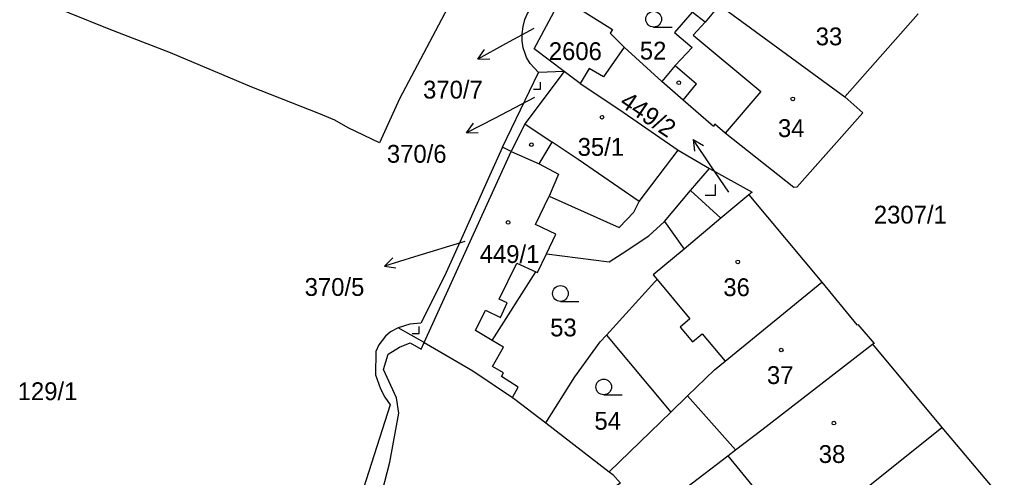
# Model space of a CAD drawing. Extents: x -679220 to -673243, y -1075091 to -1066557.
# Drawn here: x -676654 to -676560.9, y -1071402.6 to -1071358.9 of the extents above; entities that cross this region are included whole.
import ezdxf

# ---------------------------------------------------------------- set-up
doc = ezdxf.new("R2010")
doc.units = 0
for name, color, linetype in [('Hranice parcel', 7, 'Continuous'), ('Parcelní čísla', 7, 'Continuous'), ('Pop  PČ popisy', 7, 'Continuous'), ('Vnitřní kresba', 7, 'Continuous'), ('Značky budov', 7, 'Continuous'), ('Značky kultur', 7, 'Continuous')]:
    doc.layers.add(name, color=color, linetype=linetype)

msp = doc.modelspace()

# ---------------------------------------------------------------- linework, layer by layer
at = {"layer": 'Hranice parcel'}
for p, q in [((-676568.31, -1071358.37), (-676575.3, -1071366.28)), ((-676592.76, -1071364.8), (-676596.34, -1071361.54)), ((-676604.52, -1071363.95), (-676605.31, -1071363.11)), ((-676607.93, -1071371.09), (-676604.52, -1071363.95)), ((-676602.05, -1071363.86), (-676604.52, -1071363.95)), ((-676600.53, -1071365), (-676602.05, -1071363.86)), ((-676615.42, -1071389.7), (-676607.13, -1071371.5)), ((-676607.13, -1071371.5), (-676607.93, -1071371.09)), ((-676591.2, -1071371.36), (-676588.21, -1071373.1)), ((-676584.46, -1071375.63), (-676577.5, -1071383.95)), ((-676592.51, -1071378.17), (-676590.63, -1071380.8)), ((-676615.42, -1071389.7), (-676617.88, -1071388.31)), ((-676598.04, -1071389), (-676591.9, -1071396.34)), ((-676572.66, -1071389.87), (-676566.05, -1071397.82)), ((-676591.9, -1071396.34), (-676597.79, -1071402.04)), ((-676603.81, -1071397.35), (-676597.79, -1071402.04)), ((-676574.86, -1071404.84), (-676566.05, -1071397.82)), ((-676566.05, -1071397.82), (-676558.15, -1071407.15))]:
    msp.add_line(p, q, dxfattribs=at)
for points in [[(-676610.67, -1071352.37), (-676612.63, -1071356.71), (-676617.76, -1071366.46), (-676619.68, -1071370.65), (-676622.67, -1071369.24), (-676623.92, -1071368.49), (-676625.45, -1071367.86), (-676631.86, -1071365.36), (-676639.6, -1071362.09), (-676645.45, -1071359.81), (-676653.02, -1071356.73)], [(-676605.31, -1071363.11), (-676605.644, -1071362.522), (-676605.764, -1071362.245), (-676605.966, -1071361.599), (-676606.07, -1071360.93), (-676606.077, -1071360.268), (-676605.987, -1071359.569), (-676605.8, -1071358.89), (-676605.552, -1071358.315), (-676605.215, -1071357.786), (-676604.799, -1071357.318), (-676604.761, -1071357.281), (-676604.27, -1071356.892), (-676603.723, -1071356.585), (-676603.135, -1071356.37), (-676602.52, -1071356.25)], [(-676602.05, -1071363.86), (-676604.91, -1071361.71), (-676602.33, -1071356.8), (-676600.25, -1071358.11)], [(-676587.35, -1071357.64), (-676588.63, -1071359.16), (-676589.87, -1071358.19), (-676591.54, -1071360.13), (-676589.87, -1071361.56), (-676591.49, -1071363.3), (-676592.76, -1071364.8)], [(-676587.35, -1071357.64), (-676587.24, -1071357.52), (-676575.3, -1071366.28)], [(-676600.25, -1071358.11), (-676597.47, -1071359.85), (-676597.69, -1071360.21), (-676596.34, -1071361.54)], [(-676596.34, -1071361.54), (-676598.33, -1071364.37), (-676599.68, -1071363.56), (-676600.53, -1071365)], [(-676602.05, -1071363.86), (-676605.8, -1071368.85), (-676607.13, -1071371.5)], [(-676600.53, -1071365), (-676596.84, -1071367.45), (-676591.2, -1071371.36)], [(-676575.3, -1071366.28), (-676573.58, -1071367.8), (-676579.87, -1071374.9), (-676580.18, -1071374.91), (-676586.72, -1071369.74), (-676587.7, -1071368.89), (-676587.83, -1071369.1), (-676590.72, -1071366.58), (-676592.76, -1071364.8)], [(-676607.93, -1071371.09), (-676609.2, -1071373.82), (-676611.68, -1071379.45), (-676613.49, -1071383.37), (-676615.74, -1071387.86), (-676616.79, -1071387.96), (-676617.88, -1071388.31)], [(-676607.13, -1071371.5), (-676604.45, -1071372.65), (-676602.6, -1071373.65), (-676603.48, -1071375.76), (-676596.81, -1071378.73), (-676595.42, -1071377.26), (-676594.93, -1071376.27), (-676591.2, -1071371.36)], [(-676592.51, -1071378.17), (-676590.02, -1071375.2), (-676588.21, -1071373.1)], [(-676588.21, -1071373.1), (-676584.13, -1071375.35), (-676584.46, -1071375.63)], [(-676584.46, -1071375.63), (-676587.13, -1071377.86), (-676590.63, -1071380.8)], [(-676607, -1071394.96), (-676606.44, -1071393.97), (-676608.03, -1071392.93), (-676607.84, -1071392.6), (-676608.89, -1071392), (-676607.84, -1071390.16), (-676608.92, -1071389.51), (-676604.76, -1071382.97), (-676604.6, -1071383.04), (-676603.74, -1071381.24), (-676597.79, -1071382.01), (-676596.53, -1071381.2), (-676594, -1071379.54), (-676592.51, -1071378.17)], [(-676590.63, -1071380.8), (-676593.58, -1071383.26), (-676593.21, -1071383.7), (-676593.42, -1071383.92), (-676598.04, -1071389)], [(-676591.9, -1071396.34), (-676590.29, -1071394.78), (-676587.74, -1071392.31), (-676586.71, -1071391.48), (-676577.5, -1071383.95)], [(-676577.5, -1071383.95), (-676574.16, -1071388.03), (-676574.08, -1071387.97), (-676572.5, -1071389.8), (-676572.66, -1071389.87)], [(-676617.88, -1071388.31), (-676618.61, -1071388.69), (-676619.11, -1071389.11), (-676619.75, -1071389.94), (-676620.01, -1071390.56), (-676620.07, -1071392.77), (-676619.59, -1071394.13), (-676619.18, -1071394.93), (-676618.66, -1071395.65), (-676627.3, -1071422.68), (-676627.95, -1071422.94), (-676629.15, -1071423.95)], [(-676603.81, -1071397.35), (-676601.05, -1071392.98), (-676598.62, -1071389.64), (-676598.04, -1071389)], [(-676625.45, -1071424.7), (-676624.15, -1071420.38), (-676622.13, -1071413.98), (-676620.04, -1071407.23), (-676619.66, -1071404.92), (-676618.7, -1071401.1), (-676617.84, -1071396.43), (-676618.04, -1071394.99), (-676619.3, -1071392.29), (-676618.86, -1071390.8), (-676617.78, -1071390.15), (-676616.76, -1071389.74), (-676615.7, -1071390.33), (-676615.42, -1071389.7)], [(-676615.42, -1071389.7), (-676613.81, -1071390.61), (-676610.76, -1071392.4), (-676607, -1071394.96)], [(-676594.27, -1071406.5), (-676586.46, -1071400.51), (-676585.72, -1071399.94), (-676583.23, -1071398.03), (-676572.66, -1071389.87)], [(-676607, -1071394.96), (-676606.76, -1071395.12), (-676603.81, -1071397.35)], [(-676597.79, -1071402.04), (-676597.44, -1071402.3), (-676596.7, -1071403.12), (-676597.65, -1071403.73), (-676596.42, -1071405.3), (-676596.62, -1071405.46), (-676595.55, -1071407.49)]]:
    msp.add_lwpolyline(points, dxfattribs=at)
at = {"layer": 'Pop  PČ popisy'}
for p, q in [((-676604.96, -1071359.75), (-676607.66, -1071361.23)), ((-676607.66, -1071361.23), (-676610.285, -1071362.685)), ((-676610.285, -1071362.685), (-676609.652, -1071361.761)), ((-676610.285, -1071362.685), (-676609.166, -1071362.637)), ((-676604.89, -1071366.34), (-676608.71, -1071368.33)), ((-676608.71, -1071368.33), (-676611.384, -1071369.692)), ((-676611.384, -1071369.692), (-676610.719, -1071368.792)), ((-676611.384, -1071369.692), (-676610.264, -1071369.684)), ((-676588.09, -1071372.84), (-676589.768, -1071370.352)), ((-676589.768, -1071370.352), (-676588.793, -1071370.902)), ((-676589.768, -1071370.352), (-676589.623, -1071371.462)), ((-676586.38, -1071375.36), (-676588.09, -1071372.84)), ((-676611.55, -1071380.06), (-676616.34, -1071381.53)), ((-676616.34, -1071381.53), (-676619.21, -1071382.407)), ((-676619.21, -1071382.407), (-676618.399, -1071381.636)), ((-676619.21, -1071382.407), (-676618.106, -1071382.593))]:
    msp.add_line(p, q, dxfattribs=at)
at = {"layer": 'Vnitřní kresba'}
for p, q in [((-676588.63, -1071359.16), (-676589.77, -1071360.4)), ((-676589.77, -1071360.4), (-676583.31, -1071365.75)), ((-676591.49, -1071363.3), (-676589.44, -1071365.05)), ((-676590.72, -1071366.58), (-676589.44, -1071365.05)), ((-676583.31, -1071365.75), (-676586.72, -1071369.74)), ((-676605.8, -1071368.85), (-676603.22, -1071370.61)), ((-676604.45, -1071372.65), (-676603.22, -1071370.61)), ((-676600.73, -1071372.24), (-676603.22, -1071370.61)), ((-676594.93, -1071376.27), (-676600.73, -1071372.24)), ((-676590.02, -1071375.2), (-676587.13, -1071377.86)), ((-676604.79, -1071378.44), (-676603.48, -1071375.76)), ((-676602.85, -1071379.37), (-676604.79, -1071378.44)), ((-676603.74, -1071381.24), (-676602.85, -1071379.37)), ((-676608.26, -1071385.58), (-676606.57, -1071382.13)), ((-676606.57, -1071382.13), (-676604.76, -1071382.97)), ((-676593.21, -1071383.7), (-676590.08, -1071387.45)), ((-676607.51, -1071385.93), (-676608.26, -1071385.58)), ((-676610.51, -1071388.57), (-676609.56, -1071386.63)), ((-676609.56, -1071386.63), (-676608.15, -1071387.32)), ((-676608.15, -1071387.32), (-676607.51, -1071385.93)), ((-676590.08, -1071387.45), (-676591.02, -1071388.23)), ((-676591.02, -1071388.23), (-676589.83, -1071389.65)), ((-676608.92, -1071389.51), (-676610.51, -1071388.57)), ((-676589.83, -1071389.65), (-676588.9, -1071388.87)), ((-676588.9, -1071388.87), (-676586.71, -1071391.48)), ((-676590.29, -1071394.78), (-676585.72, -1071399.94)), ((-676586.46, -1071400.51), (-676582.93, -1071404.81))]:
    msp.add_line(p, q, dxfattribs=at)
at = {"layer": 'Značky budov'}
for centre in [(-676591.137, -1071364.929), (-676580.267, -1071366.469), (-676598.457, -1071368.219), (-676605.187, -1071370.839), (-676607.417, -1071378.249), (-676585.507, -1071382.019), (-676581.367, -1071390.419), (-676576.347, -1071397.389)]:
    msp.add_circle(centre, 0.175, dxfattribs=at)
at = {"layer": 'Značky kultur'}
for p, q in [((-676593.533, -1071359.62), (-676591.783, -1071359.62)), ((-676604.33, -1071365.53), (-676604.33, -1071364.86)), ((-676605.001, -1071365.53), (-676604.33, -1071365.53)), ((-676587.62, -1071375.65), (-676587.62, -1071374.65)), ((-676588.621, -1071375.65), (-676587.62, -1071375.65)), ((-676602.423, -1071385.78), (-676600.673, -1071385.78)), ((-676615.9, -1071388.84), (-676615.9, -1071388.17)), ((-676616.571, -1071388.84), (-676615.9, -1071388.84)), ((-676598.293, -1071394.69), (-676596.543, -1071394.69))]:
    msp.add_line(p, q, dxfattribs=at)
for centre in [(-676593.533, -1071358.87), (-676602.423, -1071385.03), (-676598.293, -1071393.94)]:
    msp.add_circle(centre, 0.75, dxfattribs=at)

# ---------------------------------------------------------------- texts
at = {"layer": 'Parcelní čísla'}
for s, p in [('33', (-676578.08, -1071361.36)), ('2606', (-676603.53, -1071362.769)), ('52', (-676594.85, -1071362.72)), ('370/7', (-676615.517, -1071366.438)), ('34', (-676581.68, -1071370.11)), ('370/6', (-676618.967, -1071372.558)), ('35/1', (-676600.78, -1071371.9)), ('2307/1', (-676572.537, -1071378.36)), ('449/1', (-676610.12, -1071382.12)), ('370/5', (-676626.807, -1071385.258)), ('36', (-676586.89, -1071385.279)), ('53', (-676603.4, -1071389.12)), ('37', (-676582.73, -1071393.66)), ('129/1', (-676654.17, -1071395.2)), ('54', (-676599.18, -1071398.019)), ('38', (-676577.79, -1071401.19))]:
    msp.add_text(s, height=1.7, dxfattribs=at).set_placement(p)
msp.add_text('449/2', height=1.7, rotation=326, dxfattribs=at).set_placement((-676596.884, -1071367.065))

doc.saveas('drawing.dxf')
